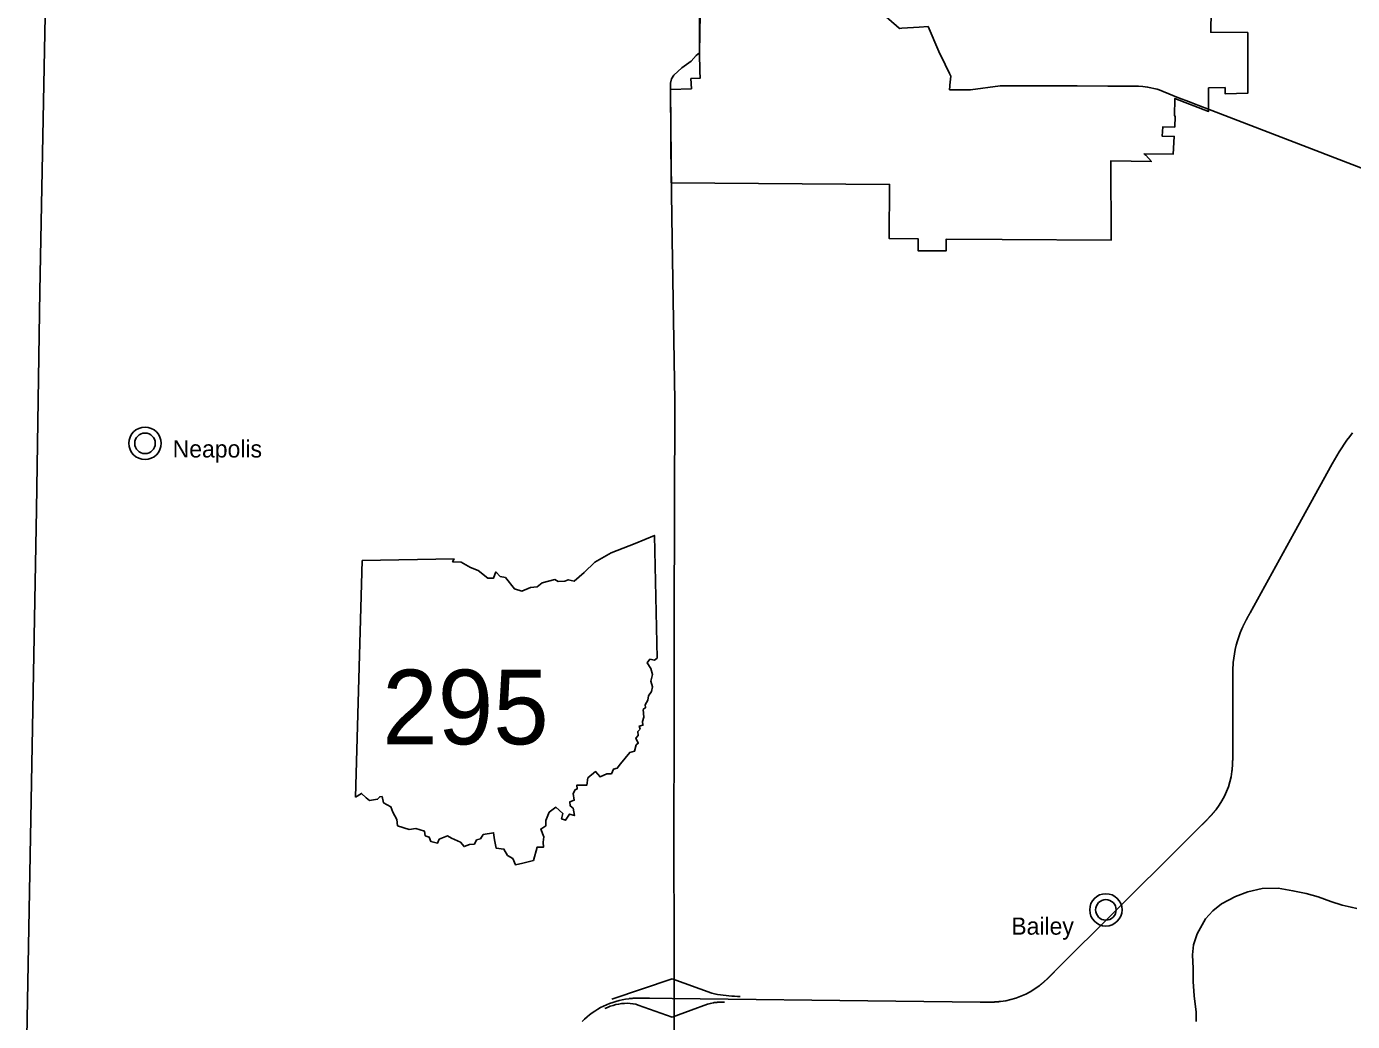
# Model space of a CAD drawing. Extents: x 0 to 750, y 0 to 507.
# Drawn here: x 115.9 to 196.4, y 88.9 to 149.3 of the extents above; entities that cross this region are included whole.
import ezdxf

# ---------------------------------------------------------------- set-up
doc = ezdxf.new("R2010")
doc.units = 0
for name, color, linetype in [('DV_X_Corp_Line', 7, 'Continuous'), ('GM_X_County', 7, 'Continuous'), ('GM_X_Rail_Line', 7, 'Continuous'), ('GM_X_State_Route', 7, 'Continuous'), ('GM_X_US_Route', 7, 'Continuous')]:
    doc.layers.add(name, color=color, linetype=linetype)

msp = doc.modelspace()

# ---------------------------------------------------------------- linework, layer by layer
at = {"layer": 'DV_X_Corp_Line'}
msp.add_lwpolyline([(187.802, 150.269), (187.772, 148.957), (190.017, 148.932), (190.019, 145.248), (188.643, 145.223), (188.643, 145.598), (187.642, 145.58), (187.643, 144.148), (185.604, 144.935), (185.576, 143.876), (185.614, 143.863), (185.591, 143.203), (184.862, 143.209), (184.828, 142.64), (185.557, 142.629), (185.488, 141.551), (183.725, 141.569), (183.773, 141.535), (183.831, 141.487), (184.174, 141.107), (181.704, 141.15), (181.741, 136.347), (175.111, 136.37), (171.727, 136.405), (171.727, 135.695), (170.012, 135.695), (170.012, 136.423), (168.251, 136.442), (168.282, 139.717), (155.035, 139.823), (154.981, 145.49), (156.257, 145.526), (156.23, 146.14), (156.785, 146.158), (156.777, 146.588), (156.757, 147.703), (156.795, 150.081)], dxfattribs=at)
for centre, radius in [((123.1, 124.009), 0.982), ((123.1, 124.009), 0.623), ((181.411, 95.696), 0.982), ((181.411, 95.696), 0.623)]:
    msp.add_circle(centre, radius, dxfattribs=at)
at = {"layer": 'GM_X_County'}
for points in [[(115.909, 86.877), (116.032, 93.503), (116.278, 106.753), (116.524, 120.001), (116.722, 133.234), (116.965, 145.776), (117.227, 159.317)], [(196.634, 95.781), (196.289, 95.857), (195.758, 95.987), (195.059, 96.209), (194.289, 96.489), (193.574, 96.692), (192.763, 96.861), (191.876, 97.007), (190.901, 96.998), (190.028, 96.782), (189.269, 96.498), (188.433, 96.071), (187.908, 95.633), (187.453, 95.148), (186.945, 94.238), (186.723, 93.573), (186.658, 92.967), (186.709, 92.137), (186.701, 91.359), (186.772, 90.484), (186.881, 89.488), (186.896, 88.92)]]:
    msp.add_lwpolyline(points, dxfattribs=at)
at = {"layer": 'GM_X_Rail_Line'}
msp.add_line((135.882, 102.541), (136.284, 116.903), dxfattribs=at)
msp.add_line((135.882, 102.541), (136.284, 116.903), dxfattribs=at)
for points in [[(136.284, 116.903), (141.856, 116.997), (141.769, 116.823), (142.295, 116.787), (142.854, 116.48), (143.326, 116.286), (143.904, 115.83), (144.25, 115.835), (144.396, 116.209), (144.661, 115.92), (144.975, 115.869), (145.518, 115.181), (145.966, 115.032), (146.503, 115.268), (146.905, 115.307), (147.198, 115.54), (147.963, 115.739), (148.176, 115.619), (148.581, 115.643), (148.785, 115.732), (149.138, 115.653), (149.76, 116.175), (150.4, 116.791), (151.384, 117.372), (152.854, 117.922), (154.016, 118.415), (154.184, 110.961)], [(136.284, 116.903), (141.856, 116.997), (141.769, 116.823), (142.295, 116.787), (142.854, 116.48), (143.326, 116.286), (143.904, 115.83), (144.25, 115.835), (144.396, 116.209), (144.661, 115.92), (144.975, 115.869), (145.518, 115.181), (145.966, 115.032), (146.503, 115.268), (146.905, 115.307), (147.198, 115.54), (147.963, 115.739), (148.176, 115.619), (148.581, 115.643), (148.785, 115.732), (149.138, 115.653), (149.76, 116.175), (150.4, 116.791), (151.384, 117.372), (152.854, 117.922), (154.016, 118.415), (154.184, 110.961)], [(154.184, 110.961), (154.013, 110.857), (153.745, 110.906), (153.566, 110.697), (153.788, 110.348), (153.893, 109.98), (153.8, 109.573), (153.892, 109.238), (153.829, 108.958), (153.662, 108.679), (153.604, 108.413), (153.461, 108.133), (153.473, 107.976), (153.337, 107.852), (153.361, 107.385), (153.293, 107.127), (153.316, 106.904), (153.096, 106.846), (153.146, 106.662), (153.006, 106.519), (153.036, 106.275), (152.877, 106.119), (153.031, 105.806), (152.907, 105.707), (152.804, 105.326), (152.521, 105.249), (151.954, 104.554), (151.754, 104.291), (151.53, 104.225), (151.406, 103.955), (151.129, 103.954), (150.711, 103.767), (150.44, 104.089), (149.966, 103.701), (149.911, 103.254), (149.312, 103.268), (149.335, 103.041), (149.202, 102.975), (149.08, 102.749), (149.15, 102.346), (148.87, 102.243), (148.904, 102.009), (149.084, 101.866), (149.163, 101.418), (148.865, 101.509), (148.621, 101.132), (148.37, 101.221), (148.452, 101.54), (148.027, 101.924), (147.626, 101.616), (147.416, 101.125), (147.414, 100.794), (147.115, 100.594), (147.306, 100.127), (147.271, 99.806), (147.277, 99.5), (146.903, 99.511), (146.677, 98.686)], [(154.184, 110.961), (154.013, 110.857), (153.745, 110.906), (153.566, 110.697), (153.788, 110.348), (153.893, 109.98), (153.8, 109.573), (153.892, 109.238), (153.829, 108.958), (153.662, 108.679), (153.604, 108.413), (153.461, 108.133), (153.473, 107.976), (153.337, 107.852), (153.361, 107.385), (153.293, 107.127), (153.316, 106.904), (153.096, 106.846), (153.146, 106.662), (153.006, 106.519), (153.036, 106.275), (152.877, 106.119), (153.031, 105.806), (152.907, 105.707), (152.804, 105.326), (152.521, 105.249), (151.954, 104.554), (151.754, 104.291), (151.53, 104.225), (151.406, 103.955), (151.129, 103.954), (150.711, 103.767), (150.44, 104.089), (149.966, 103.701), (149.911, 103.254), (149.312, 103.268), (149.335, 103.041), (149.202, 102.975), (149.08, 102.749), (149.15, 102.346), (148.87, 102.243), (148.904, 102.009), (149.084, 101.866), (149.163, 101.418), (148.865, 101.509), (148.621, 101.132), (148.37, 101.221), (148.452, 101.54), (148.027, 101.924), (147.626, 101.616), (147.416, 101.125), (147.414, 100.794), (147.115, 100.594), (147.306, 100.127), (147.271, 99.806), (147.277, 99.5), (146.903, 99.511), (146.677, 98.686)], [(146.677, 98.686), (146.026, 98.529), (145.575, 98.434), (145.416, 98.809), (145.093, 99.006), (144.883, 99.384), (144.419, 99.435), (144.309, 99.953), (144.257, 100.373), (143.624, 100.269), (143.45, 100.012), (143.225, 99.943), (143.094, 99.684), (142.788, 99.663), (142.459, 99.541), (142.244, 99.795), (141.705, 100.05), (141.463, 100.181), (140.957, 99.977), (140.849, 99.735), (140.445, 99.842), (140.351, 100.111), (140.107, 100.192), (140.053, 100.478), (139.532, 100.631), (139.133, 100.57), (138.429, 100.8), (138.387, 101.177), (138.147, 101.635), (138.022, 101.954), (137.577, 102.197), (137.487, 102.576), (137.345, 102.564), (137.215, 102.411), (136.721, 102.34), (136.524, 102.495), (136.247, 102.759), (135.882, 102.541)], [(146.677, 98.686), (146.026, 98.529), (145.575, 98.434), (145.416, 98.809), (145.093, 99.006), (144.883, 99.384), (144.419, 99.435), (144.309, 99.953), (144.257, 100.373), (143.624, 100.269), (143.45, 100.012), (143.225, 99.943), (143.094, 99.684), (142.788, 99.663), (142.459, 99.541), (142.244, 99.795), (141.705, 100.05), (141.463, 100.181), (140.957, 99.977), (140.849, 99.735), (140.445, 99.842), (140.351, 100.111), (140.107, 100.192), (140.053, 100.478), (139.532, 100.631), (139.133, 100.57), (138.429, 100.8), (138.387, 101.177), (138.147, 101.635), (138.022, 101.954), (137.577, 102.197), (137.487, 102.576), (137.345, 102.564), (137.215, 102.411), (136.721, 102.34), (136.524, 102.495), (136.247, 102.759), (135.882, 102.541)]]:
    msp.add_lwpolyline(points, dxfattribs=at)
at = {"layer": 'GM_X_State_Route'}
for points in [[(156.757, 147.971), (156.739, 152.389)], [(169.031, 149.197), (168.897, 149.188), (168.871, 149.21), (168.239, 149.757), (167.962, 149.997), (167.58, 150.328), (165.627, 151.719), (165.155, 151.986)], [(170.633, 149.298), (170.08, 149.27), (169.031, 149.197)], [(171.943, 145.683), (171.949, 145.751), (171.992, 146.294), (171.913, 146.458), (171.652, 146.994), (171.267, 147.785), (170.633, 149.298)], [(154.981, 145.49), (154.99, 145.87), (155.043, 146.135), (155.201, 146.349), (155.686, 146.789), (156.245, 147.204), (156.549, 147.551), (156.758, 147.703), (156.757, 147.971)], [(173.058, 145.469), (171.925, 145.468), (171.943, 145.683)], [(179.675, 145.696), (176.873, 145.7), (174.996, 145.7), (173.193, 145.469), (173.058, 145.469)], [(181.532, 145.692), (179.675, 145.696)], [(181.797, 145.692), (181.532, 145.692)], [(183.644, 145.656), (183.388, 145.679), (181.841, 145.692), (181.797, 145.692)], [(184.528, 145.491), (183.937, 145.63), (183.644, 145.656)], [(155.057, 139.162), (154.981, 145.49)], [(184.653, 145.461), (184.648, 145.463), (184.528, 145.491)], [(185.483, 145.11), (184.653, 145.461)], [(186.588, 144.69), (185.72, 145.01), (185.483, 145.11)], [(187.574, 144.306), (186.735, 144.636), (186.588, 144.69)], [(201.607, 138.907), (187.574, 144.306)], [(155.204, 106.817), (155.221, 113.269), (155.239, 119.977), (155.256, 126.579), (155.09, 136.394), (155.057, 139.162)], [(155.354, 71.421), (155.329, 73.45), (155.248, 80.147), (155.215, 82.836), (155.214, 86.767), (155.212, 90.807), (155.211, 92.184), (155.207, 93.44), (155.186, 99.94), (155.186, 100.098), (155.203, 106.682), (155.204, 106.817)]]:
    msp.add_lwpolyline(points, dxfattribs=at)
at = {"layer": 'GM_X_US_Route'}
for p, q in [((192.837, 118.581), (195.141, 122.766)), ((190.161, 113.72), (192.837, 118.581)), ((189.11, 105.334), (189.11, 109.633)), ((185.959, 99.581), (187.26, 100.877)), ((178.28, 91.927), (185.959, 99.581)), ((151.435, 90.276), (155.087, 91.508)), ((155.087, 91.513), (157.498, 90.648)), ((153.707, 90.345), (155.093, 90.328)), ((155.093, 90.328), (168.67, 90.161)), ((168.667, 90.161), (173.774, 90.098)), ((153.036, 89.918), (155.098, 89.178)), ((155.098, 89.177), (156.245, 89.6)), ((156.245, 89.6), (157.241, 89.968))]:
    msp.add_line(p, q, dxfattribs=at)
for centre, radius, start, end in [((207.689, 115.858), 14.324, 142.16666, 151.16666), ((195.484, 110.173), 6.366, 156.02666, 175.14), ((184.322, 104.71), 4.775, 322.40485, 352.5), ((174.457, 94.878), 4.775, 276.79325, 307.40485), ((153.024, 85.565), 4.775, 96.79325, 135.29767), ((158.143, 92.445), 1.91, 250.26056, 260.99102), ((159.34, 99.991), 9.549, 260.99102, 269.29325), ((152.398, 86.847), 3.183, 90.31321, 116.02713), ((152.391, 88.12), 1.91, 70.26056, 90.31321), ((157.902, 88.176), 1.91, 99.41825, 110.26056)]:
    msp.add_arc(centre, radius, start, end, dxfattribs=at)
for points in [[(189.667, 112.76), (189.673, 112.773), (189.679, 112.787), (189.685, 112.8), (189.691, 112.813), (189.697, 112.827), (189.703, 112.84), (189.709, 112.853), (189.715, 112.866), (189.722, 112.879), (189.728, 112.893), (189.734, 112.906), (189.74, 112.919), (189.746, 112.932), (189.753, 112.945), (189.759, 112.959), (189.765, 112.972), (189.772, 112.985), (189.778, 112.998), (189.785, 113.011), (189.791, 113.024), (189.798, 113.037), (189.804, 113.05), (189.811, 113.063), (189.817, 113.076), (189.824, 113.089), (189.83, 113.103), (189.837, 113.116), (189.843, 113.129), (189.85, 113.142), (189.857, 113.155), (189.863, 113.168), (189.87, 113.181), (189.877, 113.193), (189.883, 113.206), (189.89, 113.219), (189.897, 113.232), (189.904, 113.245), (189.91, 113.258), (189.917, 113.271), (189.924, 113.284), (189.931, 113.297), (189.938, 113.31), (189.944, 113.323), (189.951, 113.336), (189.958, 113.349), (189.965, 113.361), (189.972, 113.374), (189.979, 113.387), (189.986, 113.4), (189.993, 113.413), (190, 113.426), (190.007, 113.438), (190.014, 113.451), (190.02, 113.464), (190.027, 113.477), (190.034, 113.49), (190.041, 113.503), (190.048, 113.515), (190.055, 113.528), (190.062, 113.541), (190.069, 113.554), (190.076, 113.567), (190.083, 113.579), (190.09, 113.592), (190.097, 113.605), (190.104, 113.618), (190.111, 113.631), (190.118, 113.643), (190.126, 113.656), (190.133, 113.669), (190.14, 113.682), (190.147, 113.695), (190.154, 113.707), (190.161, 113.72)], [(189.11, 109.633), (189.11, 109.648), (189.11, 109.663), (189.11, 109.677), (189.11, 109.692), (189.11, 109.706), (189.11, 109.721), (189.11, 109.736), (189.11, 109.75), (189.11, 109.765), (189.11, 109.779), (189.11, 109.794), (189.11, 109.809), (189.11, 109.823), (189.11, 109.838), (189.11, 109.852), (189.11, 109.867), (189.111, 109.882), (189.111, 109.896), (189.111, 109.911), (189.111, 109.925), (189.111, 109.94), (189.111, 109.955), (189.111, 109.969), (189.111, 109.984), (189.111, 109.998), (189.111, 110.013), (189.112, 110.028), (189.112, 110.042), (189.112, 110.057), (189.112, 110.071), (189.112, 110.086), (189.113, 110.1), (189.113, 110.115), (189.113, 110.13), (189.113, 110.144), (189.114, 110.159), (189.114, 110.173), (189.114, 110.188), (189.115, 110.203), (189.115, 110.217), (189.115, 110.232), (189.116, 110.246), (189.116, 110.261), (189.117, 110.276), (189.117, 110.29), (189.117, 110.305), (189.118, 110.319), (189.118, 110.334), (189.119, 110.349), (189.12, 110.363), (189.12, 110.378), (189.121, 110.392), (189.121, 110.407), (189.122, 110.421), (189.123, 110.436), (189.123, 110.451), (189.124, 110.465), (189.125, 110.48), (189.126, 110.494), (189.126, 110.509), (189.127, 110.523), (189.128, 110.538), (189.129, 110.553), (189.13, 110.567), (189.131, 110.582), (189.132, 110.596), (189.133, 110.611), (189.134, 110.625), (189.135, 110.64), (189.136, 110.655), (189.137, 110.669), (189.138, 110.684), (189.139, 110.698), (189.141, 110.713)], [(189.056, 104.087), (189.058, 104.103), (189.06, 104.12), (189.062, 104.137), (189.064, 104.154), (189.066, 104.17), (189.068, 104.187), (189.07, 104.204), (189.071, 104.221), (189.073, 104.238), (189.075, 104.254), (189.077, 104.271), (189.078, 104.288), (189.08, 104.305), (189.081, 104.322), (189.083, 104.339), (189.084, 104.355), (189.085, 104.372), (189.087, 104.389), (189.088, 104.406), (189.089, 104.423), (189.09, 104.44), (189.091, 104.456), (189.092, 104.473), (189.093, 104.49), (189.094, 104.507), (189.095, 104.524), (189.096, 104.541), (189.097, 104.558), (189.098, 104.574), (189.099, 104.591), (189.099, 104.608), (189.1, 104.625), (189.101, 104.642), (189.102, 104.659), (189.102, 104.676), (189.103, 104.693), (189.103, 104.71), (189.104, 104.726), (189.104, 104.743), (189.105, 104.76), (189.105, 104.777), (189.106, 104.794), (189.106, 104.811), (189.107, 104.828), (189.107, 104.845), (189.107, 104.861), (189.108, 104.878), (189.108, 104.895), (189.108, 104.912), (189.108, 104.929), (189.109, 104.946), (189.109, 104.963), (189.109, 104.98), (189.109, 104.997), (189.109, 105.014), (189.109, 105.03), (189.109, 105.047), (189.11, 105.064), (189.11, 105.081), (189.11, 105.098), (189.11, 105.115), (189.11, 105.132), (189.11, 105.149), (189.11, 105.166), (189.11, 105.182), (189.11, 105.199), (189.11, 105.216), (189.11, 105.233), (189.11, 105.25), (189.11, 105.267), (189.11, 105.284), (189.11, 105.301), (189.11, 105.318), (189.11, 105.334)], [(187.26, 100.877), (187.272, 100.889), (187.284, 100.901), (187.296, 100.913), (187.308, 100.925), (187.319, 100.937), (187.331, 100.949), (187.343, 100.961), (187.355, 100.973), (187.367, 100.985), (187.379, 100.997), (187.391, 101.009), (187.403, 101.021), (187.415, 101.033), (187.427, 101.045), (187.439, 101.057), (187.451, 101.069), (187.463, 101.081), (187.474, 101.093), (187.486, 101.105), (187.498, 101.117), (187.51, 101.129), (187.522, 101.141), (187.534, 101.153), (187.545, 101.165), (187.557, 101.177), (187.569, 101.189), (187.581, 101.201), (187.593, 101.213), (187.604, 101.226), (187.616, 101.238), (187.628, 101.25), (187.639, 101.262), (187.651, 101.274), (187.663, 101.287), (187.674, 101.299), (187.686, 101.311), (187.697, 101.323), (187.709, 101.336), (187.721, 101.348), (187.732, 101.36), (187.744, 101.373), (187.755, 101.385), (187.766, 101.398), (187.778, 101.41), (187.789, 101.423), (187.801, 101.435), (187.812, 101.448), (187.823, 101.46), (187.835, 101.473), (187.846, 101.485), (187.857, 101.498), (187.868, 101.511), (187.879, 101.523), (187.89, 101.536), (187.902, 101.549), (187.913, 101.562), (187.924, 101.574), (187.935, 101.587), (187.946, 101.6), (187.956, 101.613), (187.967, 101.626), (187.978, 101.639), (187.989, 101.652), (188, 101.665), (188.01, 101.678), (188.021, 101.691), (188.032, 101.704), (188.042, 101.717), (188.053, 101.73), (188.063, 101.744), (188.074, 101.757), (188.084, 101.77), (188.095, 101.784), (188.105, 101.797)], [(177.357, 91.085), (177.371, 91.095), (177.384, 91.106), (177.398, 91.116), (177.411, 91.126), (177.424, 91.137), (177.437, 91.147), (177.451, 91.158), (177.464, 91.169), (177.477, 91.179), (177.49, 91.19), (177.503, 91.201), (177.516, 91.211), (177.529, 91.222), (177.542, 91.233), (177.555, 91.244), (177.568, 91.255), (177.581, 91.266), (177.593, 91.277), (177.606, 91.288), (177.619, 91.299), (177.632, 91.31), (177.645, 91.321), (177.657, 91.332), (177.67, 91.343), (177.683, 91.354), (177.695, 91.366), (177.708, 91.377), (177.72, 91.388), (177.733, 91.4), (177.745, 91.411), (177.758, 91.422), (177.77, 91.434), (177.783, 91.445), (177.795, 91.457), (177.808, 91.468), (177.82, 91.479), (177.832, 91.491), (177.845, 91.503), (177.857, 91.514), (177.869, 91.526), (177.882, 91.537), (177.894, 91.549), (177.906, 91.561), (177.918, 91.572), (177.931, 91.584), (177.943, 91.596), (177.955, 91.607), (177.967, 91.619), (177.979, 91.631), (177.991, 91.642), (178.003, 91.654), (178.016, 91.666), (178.028, 91.678), (178.04, 91.69), (178.052, 91.701), (178.064, 91.713), (178.076, 91.725), (178.088, 91.737), (178.1, 91.749), (178.112, 91.761), (178.124, 91.773), (178.136, 91.784), (178.148, 91.796), (178.16, 91.808), (178.172, 91.82), (178.184, 91.832), (178.196, 91.844), (178.208, 91.856), (178.22, 91.868), (178.232, 91.88), (178.244, 91.892), (178.256, 91.903), (178.268, 91.915), (178.28, 91.927)], [(152.459, 90.306), (152.476, 90.308), (152.493, 90.31), (152.509, 90.312), (152.526, 90.314), (152.543, 90.315), (152.56, 90.317), (152.577, 90.319), (152.593, 90.32), (152.61, 90.322), (152.627, 90.323), (152.644, 90.325), (152.661, 90.326), (152.678, 90.327), (152.694, 90.329), (152.711, 90.33), (152.728, 90.331), (152.745, 90.332), (152.762, 90.333), (152.779, 90.334), (152.796, 90.335), (152.812, 90.336), (152.829, 90.337), (152.846, 90.338), (152.863, 90.339), (152.88, 90.339), (152.897, 90.34), (152.914, 90.341), (152.93, 90.342), (152.947, 90.342), (152.964, 90.343), (152.981, 90.343), (152.998, 90.344), (153.015, 90.344), (153.032, 90.345), (153.049, 90.345), (153.066, 90.346), (153.082, 90.346), (153.099, 90.346), (153.116, 90.347), (153.133, 90.347), (153.15, 90.347), (153.167, 90.347), (153.184, 90.348), (153.201, 90.348), (153.218, 90.348), (153.234, 90.348), (153.251, 90.348), (153.268, 90.348), (153.285, 90.348), (153.302, 90.348), (153.319, 90.348), (153.336, 90.348), (153.353, 90.348), (153.37, 90.348), (153.386, 90.348), (153.403, 90.348), (153.42, 90.348), (153.437, 90.348), (153.454, 90.348), (153.471, 90.348), (153.488, 90.348), (153.505, 90.347), (153.522, 90.347), (153.539, 90.347), (153.555, 90.347), (153.572, 90.347), (153.589, 90.347), (153.606, 90.346), (153.623, 90.346), (153.64, 90.346), (153.657, 90.346), (153.674, 90.346), (153.691, 90.345), (153.707, 90.345)], [(173.774, 90.098), (173.79, 90.097), (173.807, 90.097), (173.824, 90.097), (173.841, 90.097), (173.858, 90.097), (173.875, 90.096), (173.892, 90.096), (173.909, 90.096), (173.926, 90.096), (173.942, 90.096), (173.959, 90.095), (173.976, 90.095), (173.993, 90.095), (174.01, 90.095), (174.027, 90.095), (174.044, 90.095), (174.061, 90.095), (174.078, 90.095), (174.094, 90.095), (174.111, 90.094), (174.128, 90.094), (174.145, 90.094), (174.162, 90.094), (174.179, 90.094), (174.196, 90.094), (174.213, 90.095), (174.23, 90.095), (174.246, 90.095), (174.263, 90.095), (174.28, 90.095), (174.297, 90.095), (174.314, 90.095), (174.331, 90.096), (174.348, 90.096), (174.365, 90.096), (174.382, 90.096), (174.398, 90.097), (174.415, 90.097), (174.432, 90.097), (174.449, 90.098), (174.466, 90.098), (174.483, 90.099), (174.5, 90.099), (174.517, 90.1), (174.534, 90.1), (174.55, 90.101), (174.567, 90.102), (174.584, 90.102), (174.601, 90.103), (174.618, 90.104), (174.635, 90.105), (174.652, 90.106), (174.669, 90.107), (174.685, 90.108), (174.702, 90.109), (174.719, 90.11), (174.736, 90.111), (174.753, 90.112), (174.77, 90.113), (174.787, 90.114), (174.803, 90.115), (174.82, 90.117), (174.837, 90.118), (174.854, 90.12), (174.871, 90.121), (174.888, 90.123), (174.904, 90.124), (174.921, 90.126), (174.938, 90.127), (174.955, 90.129), (174.972, 90.131), (174.988, 90.133), (175.005, 90.135), (175.022, 90.137)], [(157.589, 90.06), (157.598, 90.062), (157.607, 90.063), (157.616, 90.064), (157.625, 90.066), (157.634, 90.067), (157.644, 90.068), (157.653, 90.069), (157.662, 90.071), (157.671, 90.072), (157.68, 90.073), (157.689, 90.074), (157.698, 90.075), (157.707, 90.076), (157.716, 90.077), (157.725, 90.078), (157.734, 90.079), (157.743, 90.08), (157.752, 90.08), (157.761, 90.081), (157.77, 90.082), (157.78, 90.083), (157.789, 90.083), (157.798, 90.084), (157.807, 90.085), (157.816, 90.085), (157.825, 90.086), (157.834, 90.087), (157.843, 90.087), (157.852, 90.088), (157.861, 90.088), (157.871, 90.088), (157.88, 90.089), (157.889, 90.089), (157.898, 90.09), (157.907, 90.09), (157.916, 90.09), (157.925, 90.091), (157.934, 90.091), (157.944, 90.091), (157.953, 90.091), (157.962, 90.092), (157.971, 90.092), (157.98, 90.092), (157.989, 90.092), (157.998, 90.092), (158.007, 90.092), (158.016, 90.093), (158.026, 90.093), (158.035, 90.093), (158.044, 90.093), (158.053, 90.093), (158.062, 90.093), (158.071, 90.093), (158.08, 90.093), (158.089, 90.093), (158.099, 90.093), (158.108, 90.093), (158.117, 90.093), (158.126, 90.093), (158.135, 90.093), (158.144, 90.093), (158.153, 90.093), (158.162, 90.093), (158.172, 90.092), (158.181, 90.092), (158.19, 90.092), (158.199, 90.092), (158.208, 90.092), (158.217, 90.092), (158.226, 90.092), (158.235, 90.092), (158.245, 90.092), (158.254, 90.092), (158.263, 90.091)]]:
    msp.add_spline(points, degree=3, dxfattribs=at)

# ---------------------------------------------------------------- texts
at = {"layer": 'DV_X_Corp_Line'}
for s, p in [('Neapolis', (124.78, 123.149)), ('Bailey', (175.672, 94.191))]:
    msp.add_text(s, height=1.0417, rotation=0.00001, dxfattribs=at).set_placement(p)
at = {"layer": 'GM_X_Rail_Line'}
msp.add_text('295', height=4.5281, dxfattribs=at).set_placement((137.498, 105.743))

doc.saveas('drawing.dxf')
